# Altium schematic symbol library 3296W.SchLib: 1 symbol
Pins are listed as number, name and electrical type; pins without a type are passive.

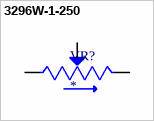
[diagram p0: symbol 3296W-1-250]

## 3296W-1-250
designator VR?
25 Ohms 0.5W, 1/2W PC Pins Through Hole Trimmer Potentiometer Cermet 25 Turn Top Adjustment; MP: 3296W-1-250; MF: Bourns
footprint TRIM_3296W-1-250
pins: 1 CCW, 2 WIPER, 3 CW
